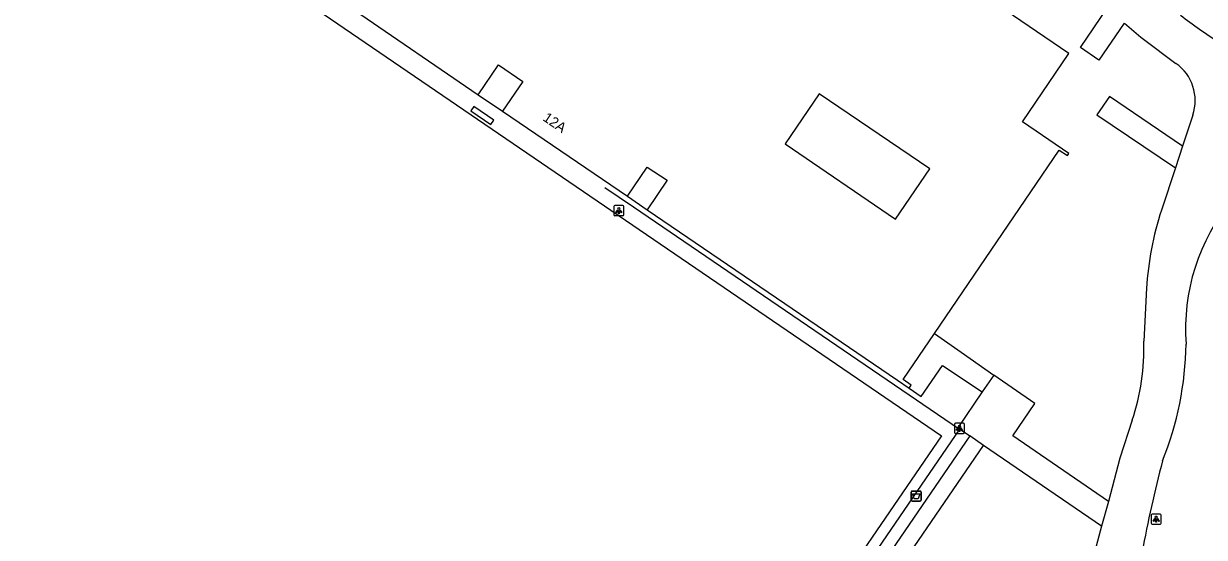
# Model space of a CAD drawing. Extents: x 157154 to 159278, y 385000 to 386650.
# Drawn here: x 158545.8 to 158662.9, y 385678.1 to 385729.1 of the extents above; entities that cross this region are included whole.
import ezdxf

# ---------------------------------------------------------------- set-up
doc = ezdxf.new("R2010")
doc.units = 0
for name, color, linetype in [('IMGEO_Afvalbak', 7, 'Continuous'), ('IMGEO_Hek', 7, 'Continuous'), ('IMGEO_Lichtpunt', 7, 'Continuous'), ('IMGEO_Pand', 7, 'Continuous'), ('IMGEO_Pand_nummerreeks', 7, 'Continuous'), ('IMGEO_Rijbaan_lokaal_open', 7, 'Continuous'), ('IMGEO_Voetpad_op_trap', 7, 'Continuous'), ('IMGEO_Voetpad_open', 7, 'Continuous')]:
    doc.layers.add(name, color=color, linetype=linetype)

msp = doc.modelspace()

# ---------------------------------------------------------------- linework, layer by layer
at = {"layer": 'IMGEO_Afvalbak'}
for p, q in [((158633.79, 385681.83), (158633.79, 385682.63)), ((158633.79, 385682.63), (158633.79, 385681.83)), ((158633.89, 385682.73), (158634.68, 385682.73)), ((158634.68, 385682.73), (158633.89, 385682.73)), ((158634.78, 385682.63), (158634.78, 385681.83)), ((158634.78, 385681.83), (158634.78, 385682.63)), ((158634.68, 385681.73), (158633.89, 385681.73)), ((158633.89, 385681.73), (158634.68, 385681.73))]:
    msp.add_line(p, q, dxfattribs=at)
msp.add_lwpolyline([(158633.93, 385682.44), (158634.64, 385682.44), (158634.49, 385681.97), (158634.08, 385681.97), (158633.93, 385682.44)], dxfattribs=at)
for centre, start, end in [((158633.89, 385682.63), 90, 180), ((158633.89, 385682.63), 90, 180), ((158634.68, 385682.63), 0, 90), ((158634.68, 385682.63), 360, 90), ((158633.89, 385681.83), 180, 270), ((158633.89, 385681.83), 180, 270), ((158634.68, 385681.83), 270, 0), ((158634.68, 385681.83), 270, 0)]:
    msp.add_arc(centre, 0.1, start, end, dxfattribs=at)
at = {"layer": 'IMGEO_Hek'}
for points in [[(158606.24, 385710.93), (158638.57, 385688.87), (158594.36, 385624.21), (158499.96, 385688.61), (158544.11, 385753.34), (158575.57, 385731.92)], [(158603.43, 385712.84), (158606.24, 385710.93)]]:
    msp.add_lwpolyline(points, dxfattribs=at)
at = {"layer": 'IMGEO_Lichtpunt'}
for p, q in [((158604.3, 385710.95), (158604.3, 385710.14)), ((158604.3, 385710.95), (158604.3, 385710.14)), ((158605.2, 385711.05), (158604.4, 385711.05)), ((158605.2, 385711.05), (158604.4, 385711.05)), ((158605.3, 385710.14), (158605.3, 385710.95)), ((158605.3, 385710.14), (158605.3, 385710.95)), ((158604.4, 385710.05), (158605.2, 385710.05)), ((158604.4, 385710.05), (158605.2, 385710.05)), ((158638.07, 385689.35), (158638.07, 385688.55)), ((158638.07, 385689.35), (158638.07, 385688.55)), ((158638.98, 385689.45), (158638.17, 385689.45)), ((158638.98, 385689.45), (158638.17, 385689.45)), ((158638.17, 385688.45), (158638.98, 385688.45)), ((158638.17, 385688.45), (158638.98, 385688.45)), ((158639.07, 385688.55), (158639.07, 385689.35)), ((158639.07, 385688.55), (158639.07, 385689.35)), ((158657.58, 385680.35), (158657.58, 385679.54)), ((158657.58, 385680.35), (158657.58, 385679.54)), ((158658.49, 385680.45), (158657.68, 385680.45)), ((158658.49, 385680.45), (158657.68, 385680.45)), ((158658.58, 385679.54), (158658.58, 385680.35)), ((158658.58, 385679.54), (158658.58, 385680.35)), ((158657.68, 385679.45), (158658.49, 385679.45)), ((158657.68, 385679.45), (158658.49, 385679.45))]:
    msp.add_line(p, q, dxfattribs=at)
for points in [[(158604.68, 385710.61), (158604.71, 385710.59), (158604.53, 385710.32), (158604.49, 385710.35), (158604.68, 385710.61)], [(158604.78, 385710.57), (158604.82, 385710.57), (158604.82, 385710.24), (158604.78, 385710.24), (158604.78, 385710.57)], [(158604.89, 385710.59), (158604.93, 385710.61), (158605.11, 385710.35), (158605.07, 385710.32), (158604.89, 385710.59)], [(158638.45, 385689.02), (158638.49, 385688.99), (158638.3, 385688.73), (158638.26, 385688.76), (158638.45, 385689.02)], [(158638.55, 385688.97), (158638.6, 385688.97), (158638.6, 385688.65), (158638.55, 385688.65), (158638.55, 385688.97)], [(158638.66, 385688.99), (158638.7, 385689.02), (158638.89, 385688.75), (158638.85, 385688.73), (158638.66, 385688.99)], [(158657.96, 385680.01), (158658, 385679.99), (158657.81, 385679.72), (158657.77, 385679.75), (158657.96, 385680.01)], [(158658.06, 385679.97), (158658.11, 385679.97), (158658.11, 385679.64), (158658.06, 385679.64), (158658.06, 385679.97)], [(158658.17, 385679.99), (158658.21, 385680.01), (158658.39, 385679.75), (158658.36, 385679.72), (158658.17, 385679.99)]]:
    msp.add_lwpolyline(points, dxfattribs=at)
for centre in [(158604.8, 385710.75), (158638.57, 385689.15), (158658.08, 385680.15)]:
    msp.add_circle(centre, 0.0994, dxfattribs=at)
for centre, start, end in [((158604.4, 385710.95), 90, 180), ((158604.4, 385710.95), 90, 180), ((158605.2, 385710.95), 0, 90), ((158605.2, 385710.95), 0, 90), ((158604.4, 385710.14), 180, 270), ((158604.4, 385710.14), 180, 270), ((158605.2, 385710.14), 270, 0), ((158605.2, 385710.14), 270, 360), ((158638.17, 385689.35), 90, 180), ((158638.17, 385689.35), 90, 180), ((158638.17, 385688.55), 180, 270), ((158638.17, 385688.55), 180, 270), ((158638.98, 385689.35), 0, 90), ((158638.98, 385689.35), 0, 90), ((158638.98, 385688.55), 270, 0), ((158638.98, 385688.55), 270, 360), ((158657.68, 385680.35), 90, 180), ((158657.68, 385680.35), 90, 180), ((158658.49, 385680.35), 0, 90), ((158658.49, 385680.35), 0, 90), ((158657.68, 385679.54), 180, 270), ((158657.68, 385679.54), 180, 270), ((158658.49, 385679.54), 270, 0), ((158658.49, 385679.54), 270, 360)]:
    msp.add_arc(centre, 0.0946, start, end, dxfattribs=at)
at = {"layer": 'IMGEO_Pand'}
for points in [[(158636.1, 385698.35), (158648.47, 385716.55), (158649.29, 385716.02), (158649.41, 385716.21), (158644.81, 385719.35), (158649.42, 385726.12), (158571.91, 385778.94), (158554.75, 385753.73)], [(158578.59, 385730.42), (158590.86, 385722.05)], [(158590.86, 385722.05), (158592.87, 385725.01), (158595.27, 385723.35), (158593.26, 385720.42)], [(158624.68, 385722.15), (158621.3, 385717.18), (158632.25, 385709.7), (158635.64, 385714.68), (158624.68, 385722.15)], [(158593.26, 385720.42), (158605.65, 385711.98)], [(158605.65, 385711.98), (158607.62, 385714.86), (158609.59, 385713.56), (158607.62, 385710.64)], [(158607.62, 385710.64), (158632.43, 385693.73), (158633.59, 385692.94)], [(158633.59, 385692.94), (158633.79, 385693.23), (158632.99, 385693.78), (158636.1, 385698.35)]]:
    msp.add_lwpolyline(points, dxfattribs=at)
at = {"layer": 'IMGEO_Rijbaan_lokaal_open'}
for points in [[(158656.81, 385727.55), (158660.02, 385725.15)], [(158661.71, 385720.03), (158660.69, 385716.95)], [(158660.69, 385716.95), (158659.98, 385714.79)], [(158659.98, 385714.79), (158658.6, 385710.6)], [(158657.13, 385702.84), (158656.87, 385697.59)], [(158655.71, 385689.76), (158654.48, 385686), (158653.34, 385681.7)], [(158653.34, 385681.7), (158652.65, 385679.24)], [(158652.65, 385679.24), (158648.99, 385665.47)]]:
    msp.add_lwpolyline(points, dxfattribs=at)
for centre, radius, start, end in [((158702.2, 385785.17), 69.22, 232.9346, 236.8215), ((158713.55, 385796.83), 89.55, 229.1043, 230.6845), ((158657.44, 385721.46), 4.51, 341.4147, 55.0256), ((158687.69, 385701.08), 30.61, 161.8844, 176.7132), ((158681.04, 385698.83), 20.05, 140.4227, 184.3506), ((158633.9, 385696.99), 22.97, 341.6663, 1.5127), ((158628.38, 385697.84), 32.67, 338.2289, 359.0656), ((158768.25, 385656.36), 113.4, 164.9958, 169.6925)]:
    msp.add_arc(centre, radius, start, end, dxfattribs=at)
at = {"layer": 'IMGEO_Voetpad_op_trap'}
msp.add_lwpolyline([(158636.1, 385698.35), (158638.75, 385696.5), (158641.99, 385694.24), (158641.98, 385694.22)], dxfattribs=at)
at = {"layer": 'IMGEO_Voetpad_open'}
for points in [[(158638.58, 385688.89), (158638.57, 385688.87), (158594.36, 385624.21), (158499.96, 385688.61), (158544.11, 385753.35)], [(158594.06, 385625.69), (158501.45, 385688.91), (158544.17, 385751.5), (158636.8, 385688.21), (158594.06, 385625.69)], [(158654.92, 385729.14), (158652.4, 385725.48), (158650.58, 385726.73), (158653.23, 385730.65)], [(158590.86, 385722.05), (158593.26, 385720.42)], [(158660.69, 385716.95), (158653.46, 385721.88), (158652.21, 385720.06), (158659.98, 385714.79)], [(158592.42, 385719.53), (158590.43, 385720.89), (158590.13, 385720.45), (158592.12, 385719.1), (158592.42, 385719.53)], [(158605.65, 385711.98), (158607.62, 385710.64)], [(158633.59, 385692.94), (158634.77, 385692.12), (158636.9, 385695.2), (158640.83, 385692.57)], [(158641.98, 385694.22), (158640.83, 385692.57)], [(158653.34, 385681.7), (158643.88, 385688.21), (158646.05, 385691.42), (158641.98, 385694.22)], [(158640.83, 385692.57), (158638.42, 385688.99), (158638.58, 385688.89)], [(158638.58, 385688.89), (158639.59, 385688.2)], [(158639.59, 385688.2), (158631, 385675.64), (158628.51, 385672)], [(158637.43, 385665.89), (158639.66, 385669.15), (158635.55, 385672), (158634.47, 385670.44), (158631.09, 385672.8), (158640.97, 385687.25)], [(158640.97, 385687.25), (158639.59, 385688.2)], [(158652.65, 385679.24), (158640.97, 385687.25)]]:
    msp.add_lwpolyline(points, dxfattribs=at)

# ---------------------------------------------------------------- texts
at = {"layer": 'IMGEO_Pand_nummerreeks'}
msp.add_text('12A', height=1, rotation=325.7314, dxfattribs=at).set_placement((158597.19, 385719.55))

doc.saveas('drawing.dxf')
